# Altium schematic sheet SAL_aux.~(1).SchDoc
size A4
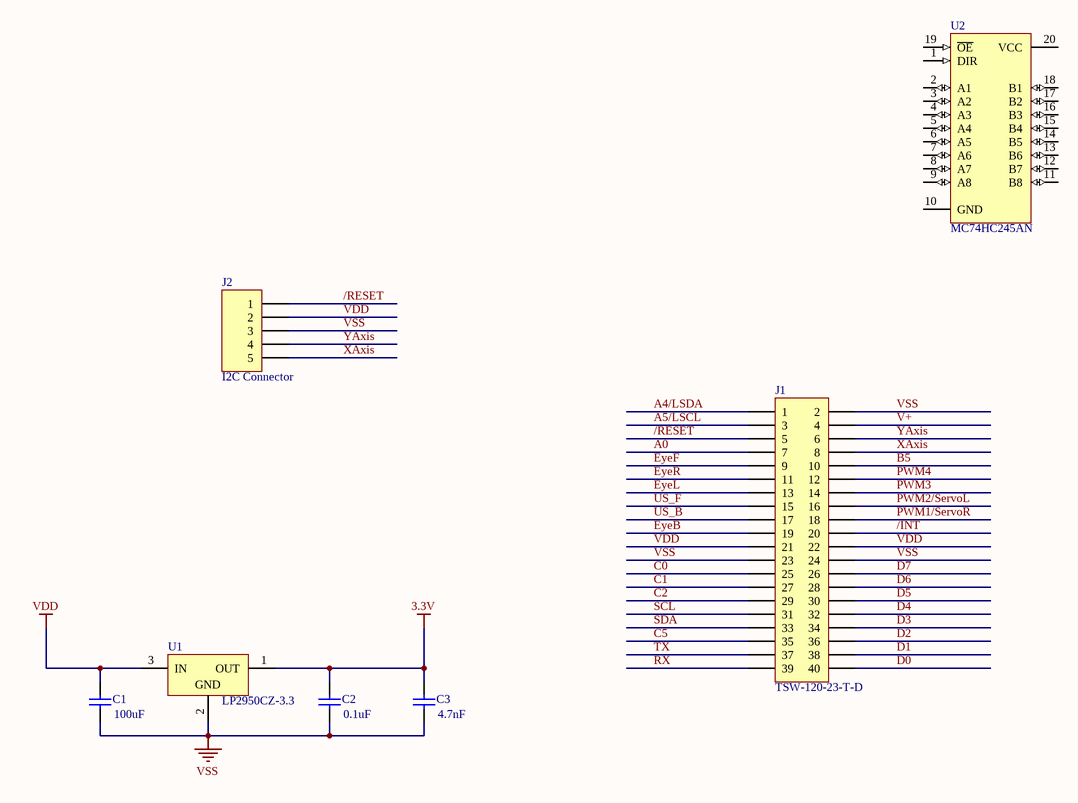
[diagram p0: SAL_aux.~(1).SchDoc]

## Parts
C1  value 100uF  [RAD-0.3]  (hidden comment: Cap)
C2  value 0.1uF  [RAD-0.3]  (hidden comment: Cap)
C3  value 4.7nF  [RAD-0.3]  (hidden comment: Cap)
J1  TSW-120-23-T-D  [SAMTEC TSW-120-XX-X-D]
J2  I2C Connector  [TYCO 640456-5]
U1  LP2950CZ-3.3  [Z03A]
U2  MC74HC245AN  [738-03]

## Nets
3.3V: C2.2 C3.2 U1.1(OUT)
VDD: C1.2 J1.21 J1.22 J2.2 U1.3(IN)
VSS: C1.1 C2.1 C3.1 J1.2 J1.23 J1.24 J2.3 U1.2(GND)
/INT: J1.20
/RESET: J1.5 J2.1
A0: J1.7
A4/LSDA: J1.1
A5/LSCL: J1.3
B5: J1.10
C0: J1.25
C1: J1.27
C2: J1.29
C5: J1.35
D0: J1.40
D1: J1.38
D2: J1.36
D3: J1.34
D4: J1.32
D5: J1.30
D6: J1.28
D7: J1.26
EyeB: J1.19
EyeF: J1.9
EyeL: J1.13
EyeR: J1.11
PWM1/ServoR: J1.18
PWM2/ServoL: J1.16
PWM3: J1.14
PWM4: J1.12
RX: J1.39
SCL: J1.31
SDA: J1.33
TX: J1.37
US_B: J1.17
US_F: J1.15
V+: J1.4
XAxis: J1.8 J2.5
YAxis: J1.6 J2.4

Not connected (* = marked no-connect by the designer): U2 1(DIR) 2(A1) 3(A2) 4(A3) 5(A4) 6(A5) 7(A6) 8(A7) 9(A8) 10(GND) 11(B8) 12(B7) 13(B6) 14(B5) 15(B4) 16(B3) 17(B2) 18(B1) 19(~{OE}) 20(VCC)

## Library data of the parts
C1-C3 = Cap: Capacitor
J1 = SAMTEC TSW-120-07-G-D: 40 pin 2.54mm pitch dual row header
J2 = TYCO 640456-5
U1 = LP2950CZ-3.3: Series of Adjustable Micropower Voltage Regulators; Manufacturer: National Semiconductor; CompType: LDO IC; PackageTopMarking: NSXYTT*2950*CZ3.3
U2 = MC74HC245AN: Octal 3-State Non-Inverting Bus Transceiver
